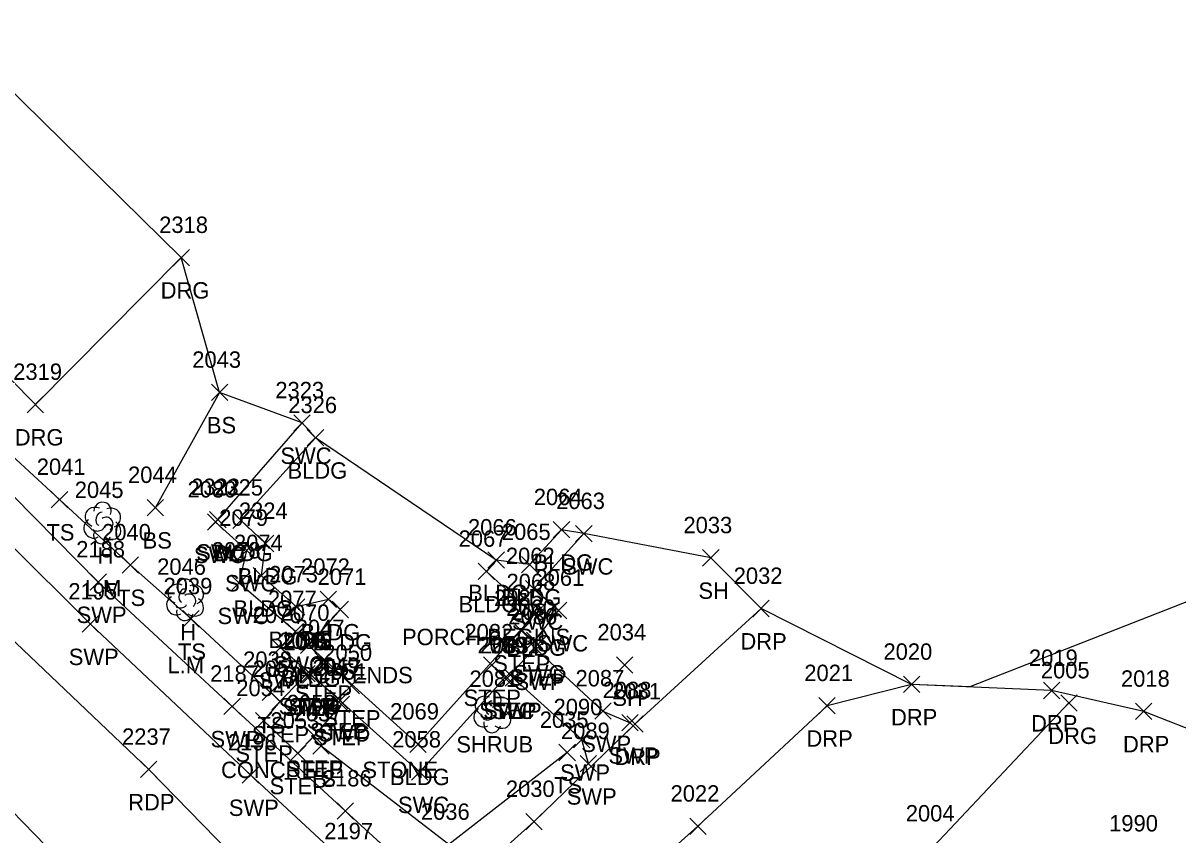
# Model space of a CAD drawing. Extents: x 1616726 to 1619875, y 273782 to 276557.
# Drawn here: x 1616834.7 to 1616975.5, y 276453.4 to 276552.4 of the extents above; entities that cross this region are included whole.
import ezdxf

# ---------------------------------------------------------------- set-up
doc = ezdxf.new("R2010")
doc.units = 0
for name, color, linetype in [('L_A', 7, 'Continuous'), ('L_C', 7, 'Continuous'), ('L_I', 7, 'Continuous'), ('L_TIC', 7, 'Continuous'), ('LBC', 7, 'Continuous'), ('LBF', 7, 'Continuous'), ('LELB', 7, 'Continuous'), ('LSH', 7, 'Continuous'), ('LSOGP', 7, 'Continuous'), ('LTD', 7, 'Continuous'), ('P_A', 7, 'Continuous'), ('P_I', 7, 'Continuous'), ('P_TIC', 7, 'Continuous'), ('PET', 7, 'Continuous'), ('PRC', 7, 'Continuous'), ('R_A', 7, 'Continuous'), ('R_I', 7, 'Continuous'), ('R_TIC', 7, 'Continuous'), ('RDG', 7, 'Continuous'), ('RDP', 7, 'Continuous'), ('RSW', 7, 'Continuous')]:
    doc.layers.add(name, color=color, linetype=linetype)

msp = doc.modelspace()

# ---------------------------------------------------------------- linework, layer by layer
at = {"layer": 'L_TIC'}
for points in [[(1616857.66, 276506.36), (1616859.66, 276508.36)], [(1616859.66, 276506.36), (1616857.66, 276508.36)], [(1616869.35, 276500.83), (1616871.35, 276502.83)], [(1616871.35, 276500.83), (1616869.35, 276502.83)], [(1616838.13, 276493.29), (1616840.13, 276495.29)], [(1616840.13, 276493.29), (1616838.13, 276495.29)], [(1616849.83, 276492.31), (1616851.83, 276494.31)], [(1616851.83, 276492.31), (1616849.83, 276494.31)], [(1616860.26, 276490.77), (1616862.26, 276492.77)], [(1616862.26, 276490.77), (1616860.26, 276492.77)], [(1616899.34, 276489.61), (1616901.34, 276491.61)], [(1616901.34, 276489.61), (1616899.34, 276491.61)], [(1616863.27, 276487.93), (1616865.27, 276489.93)], [(1616865.27, 276487.93), (1616863.27, 276489.93)], [(1616891.38, 276485.91), (1616893.38, 276487.91)], [(1616893.38, 276485.91), (1616891.38, 276487.91)], [(1616917.55, 276486.18), (1616919.55, 276488.18)], [(1616919.55, 276486.18), (1616917.55, 276488.18)], [(1616846.76, 276485.31), (1616848.76, 276487.31)], [(1616848.76, 276485.31), (1616846.76, 276487.31)], [(1616890.19, 276484.53), (1616892.19, 276486.53)], [(1616892.19, 276484.53), (1616890.19, 276486.53)], [(1616895.46, 276485.36), (1616897.46, 276487.36)], [(1616897.46, 276485.36), (1616895.46, 276487.36)], [(1616862.75, 276484), (1616864.75, 276486)], [(1616864.75, 276484), (1616862.75, 276486)], [(1616867.03, 276480.19), (1616869.03, 276482.19)], [(1616869.03, 276480.19), (1616867.03, 276482.19)], [(1616870.92, 276481.11), (1616872.92, 276483.11)], [(1616872.92, 276481.11), (1616870.92, 276483.11)], [(1616854.17, 276478.74), (1616856.17, 276480.74)], [(1616856.17, 276478.74), (1616854.17, 276480.74)], [(1616872.38, 276479.88), (1616874.38, 276481.88)], [(1616874.38, 276479.88), (1616872.38, 276481.88)], [(1616896.02, 276479.24), (1616898.02, 276481.24)], [(1616898.02, 276479.24), (1616896.02, 276481.24)], [(1616894.46, 276477.3), (1616896.46, 276479.3)], [(1616896.46, 276477.3), (1616894.46, 276479.3)], [(1616868.52, 276475.5), (1616870.52, 276477.5)], [(1616870.52, 276475.5), (1616868.52, 276477.5)], [(1616896.44, 276475.6), (1616898.44, 276477.6)], [(1616898.44, 276475.6), (1616896.44, 276477.6)], [(1616870.28, 276473.64), (1616872.28, 276475.64)], [(1616872.28, 276473.64), (1616870.28, 276475.64)], [(1616890.85, 276473.11), (1616892.85, 276475.11)], [(1616892.85, 276473.11), (1616890.85, 276475.11)], [(1616907.06, 276473.12), (1616909.06, 276475.12)], [(1616909.06, 276473.12), (1616907.06, 276475.12)], [(1616868.3, 276472.07), (1616870.3, 276474.07)], [(1616870.3, 276472.07), (1616868.3, 276474.07)], [(1616868.78, 276471.91), (1616870.78, 276473.91)], [(1616870.78, 276471.91), (1616868.78, 276473.91)], [(1616892.75, 276471.53), (1616894.75, 276473.53)], [(1616894.75, 276471.53), (1616892.75, 276473.53)], [(1616873.73, 276470.61), (1616875.73, 276472.61)], [(1616875.73, 276470.61), (1616873.73, 276472.61)], [(1616863.86, 276469.77), (1616865.86, 276471.77)], [(1616865.86, 276469.77), (1616863.86, 276471.77)], [(1616865.03, 276468.66), (1616867.03, 276470.66)], [(1616867.03, 276468.66), (1616865.03, 276470.66)], [(1616872.1, 276469.04), (1616874.1, 276471.04)], [(1616874.1, 276469.04), (1616872.1, 276471.04)], [(1616872.5, 276468.32), (1616874.5, 276470.32)], [(1616874.5, 276468.32), (1616872.5, 276470.32)], [(1616863.03, 276466.31), (1616865.03, 276468.31)], [(1616865.03, 276466.31), (1616863.03, 276468.31)], [(1616869.18, 276464.47), (1616871.18, 276466.47)], [(1616871.18, 276464.47), (1616869.18, 276466.47)], [(1616870.01, 276463.24), (1616872.01, 276465.24)], [(1616872.01, 276463.24), (1616870.01, 276465.24)], [(1616881.84, 276463.46), (1616883.84, 276465.46)], [(1616883.84, 276463.46), (1616881.84, 276465.46)], [(1616867.19, 276462.35), (1616869.19, 276464.35)], [(1616869.19, 276462.35), (1616867.19, 276464.35)], [(1616900.03, 276462.44), (1616902.03, 276464.44)], [(1616902.03, 276462.44), (1616900.03, 276464.44)]]:
    msp.add_lwpolyline(points, dxfattribs=at)
at = {"layer": 'LBC'}
msp.add_lwpolyline([(1616900.34, 276490.61), (1616896.46, 276486.36), (1616892.38, 276486.91), (1616891.19, 276485.53), (1616897.02, 276480.24), (1616882.84, 276464.46), (1616869.52, 276476.5), (1616873.38, 276480.88), (1616871.92, 276482.11), (1616868.03, 276481.19), (1616863.75, 276485), (1616864.27, 276488.93), (1616861.26, 276491.77), (1616870.35, 276501.83)], dxfattribs=at)
at = {"layer": 'LBF'}
for points in [[(1616891.85, 276474.11), (1616893.75, 276472.53), (1616897.44, 276476.6), (1616895.46, 276478.3)], [(1616871.28, 276474.64), (1616869.78, 276472.91), (1616873.1, 276470.04), (1616874.73, 276471.61)], [(1616873.5, 276469.32), (1616870.18, 276465.47), (1616868.19, 276463.35), (1616864.03, 276467.31), (1616866.03, 276469.66), (1616869.3, 276473.07)]]:
    msp.add_lwpolyline(points, dxfattribs=at)
at = {"layer": 'LELB'}
for points in [[(1616858.66, 276507.36), (1616850.83, 276493.31)], [(1616864.86, 276470.77), (1616855.17, 276479.74), (1616847.76, 276486.31), (1616839.13, 276494.29), (1616831.71, 276501.14)], [(1616901.03, 276463.44), (1616886.59, 276452.23), (1616871.01, 276464.24)]]:
    msp.add_lwpolyline(points, dxfattribs=at)
at = {"layer": 'LSH'}
msp.add_line((1616891.89, 276468.44), (1616891.89, 276468.44), dxfattribs=at)
msp.add_line((1616891.89, 276468.44), (1616891.89, 276468.44), dxfattribs=at)
msp.add_arc((1616891.93, 276469.87), 1.05, 335.5272, 180.9563, dxfattribs=at)
for centre, major_axis, ratio, start_param, end_param in [((1616891.1, 276469.11), (1.21, -0.51), 0.895232, 1.570796, 4.712389), ((1616891.68, 276468.9), (-0.208, -0.792), 0.645439, 3.141593, 6.283185), ((1616892.93, 276469.02), (-1.14, -0.48), 0.949671, 1.570796, 4.712389), ((1616890.8, 276467.73), (0.58, -1.04), 0.959034, 3.141593, 6.283185), ((1616892.39, 276468.27), (-0.5, 0.667), 0.989748, 3.141593, 6.283185), ((1616892.89, 276467.61), (-1.09, 0.79), 0.841452, 1.570796, 4.712389), ((1616891.89, 276466.94), (0.26, 1.06), 0.942809, 1.570796, 4.712389), ((1616891.43, 276467.69), (-0.625, -0.083), 0.423636, 0, 3.141593)]:
    msp.add_ellipse(centre, major_axis=major_axis, ratio=ratio, start_param=start_param, end_param=end_param, dxfattribs=at)
at = {"layer": 'LSOGP'}
msp.add_lwpolyline([(1616980.96, 276483.54), (1616950.12, 276471.44), (1616943.03, 276471.75), (1616924.67, 276481), (1616918.55, 276487.18), (1616903.07, 276490.13), (1616900.34, 276490.61), (1616896.46, 276486.36), (1616892.38, 276486.91), (1616870.35, 276501.83), (1616868.71, 276503.64), (1616858.66, 276507.36), (1616853.98, 276523.8), (1616824.85, 276552.4)], dxfattribs=at)
at = {"layer": 'LTD'}
for p, q in [((1616844.33, 276491.48), (1616844.33, 276491.48)), ((1616844.33, 276491.48), (1616844.33, 276491.48)), ((1616854.43, 276482.11), (1616854.43, 276482.11)), ((1616854.43, 276482.11), (1616854.43, 276482.11))]:
    msp.add_line(p, q, dxfattribs=at)
for centre in [(1616844.38, 276492.91), (1616854.48, 276483.55)]:
    msp.add_arc(centre, 1.05, 335.5272, 180.9563, dxfattribs=at)
for centre, major_axis, ratio, start_param, end_param in [((1616843.54, 276492.14), (1.21, -0.51), 0.895232, 1.570796, 4.712389), ((1616845.37, 276492.06), (-1.14, -0.48), 0.949671, 1.570796, 4.712389), ((1616843.25, 276490.77), (0.58, -1.04), 0.959034, 3.141593, 6.283185), ((1616844.12, 276491.94), (-0.208, -0.792), 0.645439, 3.141593, 6.283185), ((1616844.83, 276491.31), (-0.5, 0.667), 0.989748, 3.141593, 6.283185), ((1616843.87, 276490.73), (-0.625, -0.083), 0.423636, 0, 3.141593), ((1616845.33, 276490.65), (-1.09, 0.79), 0.841452, 1.570796, 4.712389), ((1616844.33, 276489.98), (0.26, 1.06), 0.942809, 1.570796, 4.712389), ((1616853.64, 276482.78), (1.21, -0.51), 0.895232, 1.570796, 4.712389), ((1616854.22, 276482.57), (-0.208, -0.792), 0.645439, 3.141593, 6.283185), ((1616855.47, 276482.69), (-1.14, -0.48), 0.949671, 1.570796, 4.712389), ((1616853.35, 276481.4), (0.58, -1.04), 0.959034, 3.141593, 6.283185), ((1616854.93, 276481.94), (-0.5, 0.667), 0.989748, 3.141593, 6.283185), ((1616855.43, 276481.28), (-1.09, 0.79), 0.841452, 1.570796, 4.712389), ((1616854.43, 276480.61), (0.26, 1.06), 0.942809, 1.570796, 4.712389), ((1616853.97, 276481.36), (-0.625, -0.083), 0.423636, 0, 3.141593)]:
    msp.add_ellipse(centre, major_axis=major_axis, ratio=ratio, start_param=start_param, end_param=end_param, dxfattribs=at)
at = {"layer": 'P_TIC'}
for points in [[(1616849.02, 276460.38), (1616851.02, 276462.38)], [(1616851.02, 276460.38), (1616849.02, 276462.38)]]:
    msp.add_lwpolyline(points, dxfattribs=at)
at = {"layer": 'PET'}
msp.add_lwpolyline([(1616787.59, 276521.58), (1616809.24, 276501.22), (1616830.38, 276480.01), (1616850.02, 276461.38), (1616866.44, 276444.54), (1616873.55, 276441.17), (1616892.87, 276425.54), (1616905.78, 276413.31), (1616922.09, 276405.95), (1616942.2, 276398.95), (1616962.48, 276398.53), (1616981.09, 276402.37)], dxfattribs=at)
at = {"layer": 'PRC'}
msp.add_lwpolyline([(1616953.09, 276321.77), (1616937.3, 276341.18), (1616917.35, 276364.38), (1616896.09, 276388.68), (1616870.6, 276416.95), (1616844.42, 276444.9), (1616816.58, 276473.52), (1616795.84, 276493.99), (1616777.17, 276512.19)], dxfattribs=at)
at = {"layer": 'R_TIC'}
for points in [[(1616852.98, 276522.8), (1616854.98, 276524.8)], [(1616854.98, 276522.8), (1616852.98, 276524.8)], [(1616835.2, 276504.88), (1616837.2, 276506.88)], [(1616837.2, 276504.88), (1616835.2, 276506.88)], [(1616867.71, 276502.64), (1616869.71, 276504.64)], [(1616869.71, 276502.64), (1616867.71, 276504.64)], [(1616857.17, 276490.54), (1616859.17, 276492.54)], [(1616859.17, 276490.54), (1616857.17, 276492.54)], [(1616857.44, 276490.84), (1616859.44, 276492.84)], [(1616859.44, 276490.84), (1616857.44, 276492.84)], [(1616902.07, 276489.13), (1616904.07, 276491.13)], [(1616904.07, 276489.13), (1616902.07, 276491.13)], [(1616860.96, 276487.08), (1616862.96, 276489.08)], [(1616862.96, 276487.08), (1616860.96, 276489.08)], [(1616842.86, 276483.23), (1616844.86, 276485.23)], [(1616844.86, 276483.23), (1616842.86, 276485.23)], [(1616860.04, 276483.1), (1616862.04, 276485.1)], [(1616862.04, 276483.1), (1616860.04, 276485.1)], [(1616895.95, 276482.42), (1616897.95, 276484.42)], [(1616897.95, 276482.42), (1616895.95, 276484.42)], [(1616923.67, 276480), (1616925.67, 276482)], [(1616925.67, 276480), (1616923.67, 276482)], [(1616898.99, 276479.76), (1616900.99, 276481.76)], [(1616900.99, 276479.76), (1616898.99, 276481.76)], [(1616841.9, 276478.1), (1616843.9, 276480.1)], [(1616843.9, 276478.1), (1616841.9, 276480.1)], [(1616866.89, 276477.18), (1616868.89, 276479.18)], [(1616868.89, 276477.18), (1616866.89, 276479.18)], [(1616896.08, 276476.1), (1616898.08, 276478.1)], [(1616898.08, 276476.1), (1616896.08, 276478.1)], [(1616865.08, 276475.23), (1616867.08, 276477.23)], [(1616867.08, 276475.23), (1616865.08, 276477.23)], [(1616896.25, 276475.06), (1616898.25, 276477.06)], [(1616898.25, 276475.06), (1616896.25, 276477.06)], [(1616868.68, 276472.05), (1616870.68, 276474.05)], [(1616870.68, 276472.05), (1616868.68, 276474.05)], [(1616892.43, 276471.53), (1616894.43, 276473.53)], [(1616894.43, 276471.53), (1616892.43, 276473.53)], [(1616893.48, 276471.52), (1616895.48, 276473.52)], [(1616895.48, 276471.52), (1616893.48, 276473.52)], [(1616942.03, 276470.75), (1616944.03, 276472.75)], [(1616944.03, 276470.75), (1616942.03, 276472.75)], [(1616872.33, 276468.78), (1616874.33, 276470.78)], [(1616874.33, 276468.78), (1616872.33, 276470.78)], [(1616959.11, 276470), (1616961.11, 276472)], [(1616961.11, 276470), (1616959.11, 276472)], [(1616859.19, 276468.07), (1616861.19, 276470.07)], [(1616861.19, 276468.07), (1616859.19, 276470.07)], [(1616904.39, 276467.5), (1616906.39, 276469.5)], [(1616906.39, 276467.5), (1616904.39, 276469.5)], [(1616931.72, 276468.15), (1616933.72, 276470.15)], [(1616933.72, 276468.15), (1616931.72, 276470.15)], [(1616961.21, 276468.48), (1616963.21, 276470.48)], [(1616963.21, 276468.48), (1616961.21, 276470.48)], [(1616970.33, 276467.46), (1616972.33, 276469.46)], [(1616972.33, 276467.46), (1616970.33, 276469.46)], [(1616907.7, 276466.07), (1616909.7, 276468.07)], [(1616909.7, 276466.07), (1616907.7, 276468.07)], [(1616908.3, 276465.91), (1616910.3, 276467.91)], [(1616910.3, 276465.91), (1616908.3, 276467.91)], [(1616901.81, 276463.99), (1616903.81, 276465.99)], [(1616903.81, 276463.99), (1616901.81, 276465.99)], [(1616902.62, 276461.08), (1616904.62, 276463.08)], [(1616904.62, 276461.08), (1616902.62, 276463.08)], [(1616861.42, 276459.7), (1616863.42, 276461.7)], [(1616863.42, 276459.7), (1616861.42, 276461.7)], [(1616882.04, 276460.05), (1616884.04, 276462.05)], [(1616884.04, 276460.05), (1616882.04, 276462.05)], [(1616872.99, 276455.3), (1616874.99, 276457.3)], [(1616874.99, 276455.3), (1616872.99, 276457.3)], [(1616895.99, 276454.02), (1616897.99, 276456.02)], [(1616897.99, 276454.02), (1616895.99, 276456.02)], [(1616915.98, 276453.45), (1616917.98, 276455.45)], [(1616917.98, 276453.45), (1616915.98, 276455.45)]]:
    msp.add_lwpolyline(points, dxfattribs=at)
at = {"layer": 'RDG'}
for points in [[(1616853.98, 276523.8), (1616836.2, 276505.88), (1616823.82, 276518.4), (1616816.9, 276511.12)], [(1616908.14, 276445.08), (1616913.85, 276439.07), (1616923.89, 276429.22), (1616945.73, 276452.03), (1616962.21, 276469.48)]]:
    msp.add_lwpolyline(points, dxfattribs=at)
at = {"layer": 'RDP'}
for points in [[(1616887.4, 276446.41), (1616896.99, 276455.02), (1616909.3, 276466.91), (1616924.67, 276481)], [(1617035.74, 276419.76), (1617032.19, 276427.66), (1617017.5, 276442.32), (1617002.8, 276454.02), (1616987.53, 276462.11), (1616971.33, 276468.46), (1616960.11, 276471), (1616943.03, 276471.75), (1616932.72, 276469.15), (1616916.98, 276454.45), (1616902.69, 276441.64), (1616898.05, 276435.6)]]:
    msp.add_lwpolyline(points, dxfattribs=at)
at = {"layer": 'RSW'}
for points in [[(1616979.18, 276402.58), (1616970.93, 276402.28), (1616960.75, 276403.53), (1616947.75, 276406.07), (1616931.67, 276410.77), (1616917.99, 276418.15), (1616909.17, 276424.63), (1616898.61, 276433.98), (1616883.06, 276447.99), (1616873.99, 276456.3), (1616860.19, 276469.07), (1616843.86, 276484.23), (1616830.87, 276497.35), (1616815.83, 276511.33), (1616796.2, 276529.55)], [(1616793, 276526.57), (1616806.64, 276513.9), (1616822.44, 276499.44), (1616842.9, 276479.1), (1616862.42, 276460.7), (1616874.12, 276449.86), (1616881.51, 276443.96), (1616898.31, 276429.07), (1616904.59, 276422.09), (1616914.85, 276414.69), (1616926.19, 276408.67), (1616938.69, 276404.25), (1616951.3, 276401.58), (1616951.76, 276400.21)], [(1616858.44, 276491.84), (1616868.71, 276503.64)], [(1616869.68, 276473.05), (1616866.08, 276476.23), (1616867.89, 276478.18), (1616861.04, 276484.1), (1616861.96, 276488.08), (1616858.17, 276491.54)], [(1616897.08, 276477.1), (1616899.99, 276480.76), (1616896.95, 276483.42), (1616903.07, 276490.13)], [(1616897.25, 276476.06), (1616905.39, 276468.5), (1616908.7, 276467.07)], [(1616873.33, 276469.78), (1616883.04, 276461.05), (1616893.43, 276472.53)], [(1616903.62, 276462.08), (1616902.81, 276464.99), (1616894.48, 276472.52)]]:
    msp.add_lwpolyline(points, dxfattribs=at)

# ---------------------------------------------------------------- texts
at = {"layer": 'L_A'}
for s, p in [('BS', (1616857.1, 276502.36)), ('BLDG', (1616866.94, 276496.83)), ('TS', (1616837.54, 276489.29)), ('BS', (1616849.27, 276488.31)), ('H', (1616843.77, 276486.48)), ('BLDG', (1616857.85, 276486.77)), ('BLDG', (1616896.93, 276485.61)), ('BLDG', (1616860.86, 276483.93)), ('TS', (1616846.17, 276481.31)), ('BLDG', (1616888.97, 276481.91)), ('BLDG', (1616893.05, 276481.36)), ('SH', (1616917.04, 276482.18)), ('BLDG', (1616860.34, 276480)), ('BLDG', (1616887.78, 276480.53)), ('H', (1616853.86, 276477.11)), ('BLDG', (1616868.52, 276477.11)), ('BLDG', (1616864.62, 276476.19)), ('BLDG', (1616869.97, 276475.88)), ('TS', (1616853.58, 276474.74)), ('BLDG', (1616893.61, 276475.24)), ('STEP', (1616892.02, 276473.3)), ('BLDG', (1616866.11, 276471.5)), ('STEP', (1616893.99, 276471.6)), ('STEP', (1616867.84, 276469.64)), ('STEP', (1616888.41, 276469.11)), ('SH', (1616906.55, 276469.12)), ('STEP', (1616865.86, 276468.07)), ('STEP', (1616866.34, 276467.91)), ('STEP', (1616890.31, 276467.53)), ('STEP', (1616871.29, 276466.61)), ('STEP', (1616862.59, 276464.66)), ('TS', (1616863.27, 276465.77)), ('STEP', (1616869.66, 276465.04)), ('STEP', (1616870.06, 276464.32)), ('SHRUB', (1616887.52, 276463.44)), ('STEP', (1616860.59, 276462.31)), ('STEP', (1616866.74, 276460.47)), ('TS', (1616869.42, 276459.24)), ('BLDG', (1616879.43, 276459.46)), ('STEP', (1616864.75, 276458.35)), ('TS', (1616899.44, 276458.44))]:
    msp.add_text(s, height=2, dxfattribs=at).set_placement(p)
at = {"layer": 'L_C'}
for s, p in [('L.M', (1616842.21, 276482.48)), ('PORCH BEGINS', (1616880.9, 276476.53)), ('L.M', (1616852.3, 276473.11)), ('PORCH ENDS', (1616864.37, 276471.88)), ('CONCRETE   STONE', (1616858.83, 276460.32))]:
    msp.add_text(s, height=2, dxfattribs=at).set_placement(p)
at = {"layer": 'L_I'}
for s, p in [('2043', (1616855.32, 276510.36)), ('2326', (1616867.03, 276504.83)), ('2041', (1616836.36, 276497.29)), ('2044', (1616847.49, 276496.31)), ('2045', (1616840.99, 276494.48)), ('2325', (1616858, 276494.77)), ('2064', (1616896.96, 276493.61)), ('2324', (1616861.01, 276491.93)), ('2066', (1616888.94, 276489.91)), ('2033', (1616915.21, 276490.18)), ('2040', (1616844.33, 276489.31)), ('2067', (1616887.8, 276488.53)), ('2065', (1616893.07, 276489.36)), ('2074', (1616860.41, 276488)), ('2046', (1616851.04, 276485.11)), ('2073', (1616864.69, 276484.19)), ('2072', (1616868.59, 276485.11)), ('2039', (1616851.82, 276482.74)), ('2071', (1616870.61, 276483.88)), ('2068', (1616893.64, 276483.24)), ('2085', (1616892.12, 276481.3)), ('2070', (1616866.1, 276479.5)), ('2084', (1616894.1, 276479.6)), ('2047', (1616867.94, 276477.64)), ('2082', (1616888.51, 276477.11)), ('2034', (1616904.72, 276477.12)), ('2056', (1616865.91, 276476.07)), ('2048', (1616866.44, 276475.91)), ('2050', (1616871.3, 276474.61)), ('2083', (1616890.41, 276475.53)), ('2038', (1616861.52, 276473.77)), ('2049', (1616869.76, 276473.04)), ('2055', (1616862.69, 276472.66)), ('2051', (1616870.73, 276472.32)), ('2081', (1616889.12, 276471.44)), ('2054', (1616860.69, 276470.31)), ('2052', (1616866.85, 276468.47)), ('2037', (1616867.67, 276467.24)), ('2069', (1616879.45, 276467.46)), ('2053', (1616864.85, 276466.35)), ('2035', (1616897.69, 276466.44)), ('2036', (1616883.2, 276455.23)), ('1990', (1616967.12, 276453.81))]:
    msp.add_text(s, height=2, dxfattribs=at).set_placement(p)
at = {"layer": 'P_A'}
msp.add_text('RDP', height=2, dxfattribs=at).set_placement((1616847.51, 276456.38))
at = {"layer": 'P_I'}
msp.add_text('2237', height=2, dxfattribs=at).set_placement((1616846.76, 276464.38))
at = {"layer": 'R_A'}
for s, p in [('DRG', (1616851.47, 276518.8)), ('DRG', (1616833.68, 276500.88)), ('SWC', (1616866.07, 276498.64)), ('SWC', (1616855.53, 276486.54)), ('SWC', (1616855.8, 276486.84)), ('SWC', (1616900.43, 276485.13)), ('SWC', (1616859.32, 276483.08)), ('SWP', (1616841.22, 276479.23)), ('SWC', (1616858.4, 276479.1)), ('SWC', (1616894.31, 276478.42)), ('SWC', (1616897.35, 276475.76)), ('DRP', (1616922.16, 276476)), ('SWP', (1616840.26, 276474.1)), ('SWC', (1616865.25, 276473.18)), ('SWC', (1616894.45, 276472.1)), ('SWC', (1616863.44, 276471.23)), ('SWP', (1616894.62, 276471.06)), ('SWC', (1616867.04, 276468.05)), ('SWC', (1616890.8, 276467.53)), ('SWP', (1616891.84, 276467.52)), ('DRP', (1616940.52, 276466.75)), ('DRP', (1616957.6, 276466)), ('SWC', (1616870.69, 276464.78)), ('DRG', (1616959.7, 276464.48)), ('SWP', (1616857.55, 276464.07)), ('SWP', (1616902.75, 276463.5)), ('DRP', (1616930.21, 276464.15)), ('DRP', (1616968.81, 276463.46)), ('SWP', (1616906.07, 276462.07)), ('DRP', (1616906.79, 276461.91)), ('SWP', (1616900.17, 276459.99)), ('SWC', (1616880.4, 276456.05)), ('SWP', (1616900.98, 276457.08)), ('SWP', (1616859.78, 276455.7))]:
    msp.add_text(s, height=2, dxfattribs=at).set_placement(p)
at = {"layer": 'R_I'}
for s, p in [('2318', (1616851.29, 276526.8)), ('2319', (1616833.49, 276508.88)), ('2323', (1616865.45, 276506.64)), ('2080', (1616854.75, 276494.54)), ('2322', (1616855.18, 276494.84)), ('2063', (1616899.69, 276493.13)), ('2079', (1616858.61, 276491.08)), ('2188', (1616841.17, 276487.23)), ('2078', (1616857.7, 276487.1)), ('2062', (1616893.56, 276486.42)), ('2061', (1616897.17, 276483.76)), ('2032', (1616921.34, 276484)), ('2195', (1616840.21, 276482.1)), ('2077', (1616864.55, 276481.18)), ('2060', (1616893.61, 276480.1)), ('2076', (1616862.69, 276479.23)), ('2086', (1616893.86, 276479.06)), ('2075', (1616866.34, 276476.05)), ('2059', (1616890.09, 276475.53)), ('2091', (1616891.71, 276475.52)), ('2020', (1616939.6, 276474.75)), ('2019', (1616957.34, 276474)), ('2187', (1616857.5, 276472.07)), ('2057', (1616869.99, 276472.78)), ('2087', (1616902.05, 276471.5)), ('2021', (1616929.95, 276472.15)), ('2005', (1616958.79, 276472.48)), ('2018', (1616968.56, 276471.46)), ('2088', (1616905.36, 276470.07)), ('2031', (1616906.53, 276469.91)), ('2090', (1616899.38, 276467.99)), ('2089', (1616900.28, 276465.08)), ('2196', (1616859.67, 276463.7)), ('2058', (1616879.7, 276464.05)), ('2186', (1616871.24, 276459.3)), ('2030', (1616893.56, 276458.02)), ('2022', (1616913.64, 276457.45)), ('2004', (1616942.32, 276455.03)), ('2197', (1616871.42, 276452.86))]:
    msp.add_text(s, height=2, dxfattribs=at).set_placement(p)

doc.saveas('drawing.dxf')
